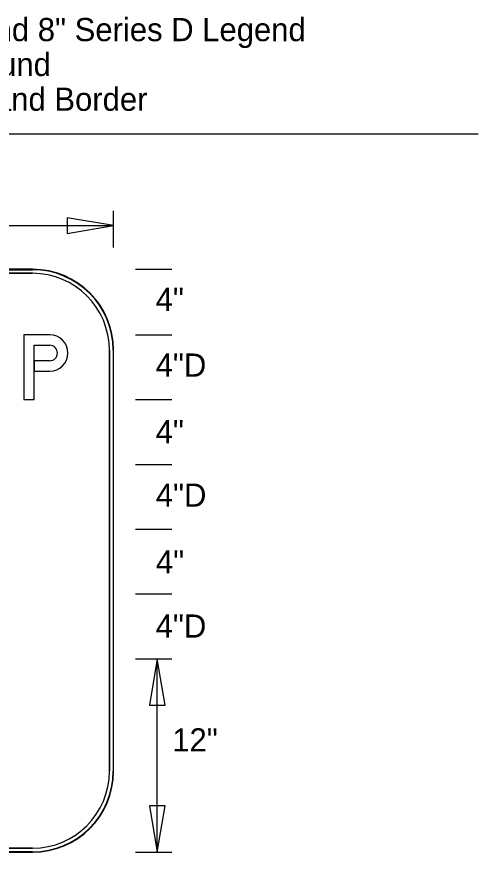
# Model space of a CAD drawing. Extents: x 0 to 770, y 0 to 495.
# Drawn here: x 700.4 to 770, y 221.6 to 347.6 of the extents above; entities that cross this region are included whole.
import ezdxf

# ---------------------------------------------------------------- set-up
doc = ezdxf.new("R2010")
doc.units = 0
for name, color, linetype in [('Dimension', 7, 'Continuous'), ('GSBWFill', 7, 'Continuous'), ('GSColorFill', 7, 'Continuous'), ('GSDims', 7, 'Continuous'), ('GSOutline', 7, 'Continuous'), ('SheetLines_dp', 7, 'Continuous'), ('TextStructures', 7, 'Continuous')]:
    doc.layers.add(name, color=color, linetype=linetype)

msp = doc.modelspace()

# ---------------------------------------------------------------- linework, layer by layer
at = {"layer": 'Dimension'}
for points in [[(714.96, 316.14), (707.95, 317.33), (707.95, 314.95)], [(721.56, 250.81), (720.37, 243.79), (722.75, 243.79)], [(721.56, 221.63), (722.75, 228.64), (720.37, 228.64)]]:
    msp.add_lwpolyline(points, close=True, dxfattribs=at)
at = {"layer": 'GSBWFill'}
for p, q in [((702.75, 309.55), (639.25, 309.55)), ((702.75, 309.55), (639.25, 309.55)), ((639.25, 308.94), (702.75, 308.94)), ((703, 298.09), (705.34, 298.09)), ((714.35, 297.34), (714.35, 233.84)), ((714.96, 233.84), (714.96, 297.34)), ((714.96, 233.84), (714.96, 297.34)), ((702.75, 222.24), (639.26, 222.24)), ((639.25, 221.63), (702.75, 221.63)), ((639.26, 221.63), (702.75, 221.63))]:
    msp.add_line(p, q, dxfattribs=at)
for points in [[(705.34, 299.66), (701.43, 299.66), (701.43, 289.89), (703, 289.89), (703, 298.09)], [(705.34, 295.75), (703, 295.75), (703, 294.19), (705.34, 294.19)]]:
    msp.add_lwpolyline(points, dxfattribs=at)
for centre, radius, start, end in [((702.75, 297.34), 12.21, 0, 90), ((702.75, 297.34), 12.21, 0, 90), ((702.75, 297.34), 11.6, 0, 90), ((705.34, 296.92), 2.74, 270, 90), ((705.34, 296.92), 1.17, 270, 90), ((702.75, 233.84), 12.21, 270, 0), ((702.75, 233.84), 11.6, 270, 0), ((702.75, 233.84), 12.21, 270, 0)]:
    msp.add_arc(centre, radius, start, end, dxfattribs=at)
at = {"layer": 'GSColorFill'}
for p, q in [((702.75, 309.55), (639.25, 309.55)), ((702.75, 309.55), (639.25, 309.55)), ((702.75, 309.55), (639.25, 309.55)), ((639.25, 309.49), (702.75, 309.49)), ((639.25, 308.94), (702.75, 308.94)), ((703, 298.09), (705.34, 298.09)), ((714.35, 297.34), (714.35, 233.84)), ((714.9, 297.34), (714.9, 233.84)), ((714.96, 233.84), (714.96, 297.34)), ((714.96, 233.84), (714.96, 297.34)), ((714.96, 233.84), (714.96, 297.34)), ((702.75, 222.24), (639.26, 222.24)), ((702.75, 221.69), (639.25, 221.69)), ((639.25, 221.63), (702.75, 221.63)), ((639.25, 221.63), (702.75, 221.63)), ((639.26, 221.63), (702.75, 221.63))]:
    msp.add_line(p, q, dxfattribs=at)
for points in [[(705.34, 299.66), (701.43, 299.66), (701.43, 289.89), (703, 289.89), (703, 298.09)], [(705.34, 295.75), (703, 295.75), (703, 294.19), (705.34, 294.19)]]:
    msp.add_lwpolyline(points, dxfattribs=at)
for centre, radius, start, end in [((702.75, 297.34), 12.21, 0, 90), ((702.75, 297.34), 12.21, 0, 90), ((702.75, 297.34), 12.21, 0, 90), ((702.75, 297.34), 12.15, 0, 90), ((702.75, 297.34), 11.6, 0, 90), ((705.34, 296.92), 2.74, 270, 90), ((705.34, 296.92), 1.17, 270, 90), ((702.75, 233.84), 12.21, 270, 0), ((702.75, 233.84), 12.21, 270, 0), ((702.75, 233.84), 11.6, 270, 0), ((702.75, 233.84), 12.21, 270, 0), ((702.75, 233.84), 12.15, 270, 0)]:
    msp.add_arc(centre, radius, start, end, dxfattribs=at)
at = {"layer": 'GSDims'}
for p, q in [((714.96, 312.85), (714.96, 318.34)), ((627.04, 316.14), (714.96, 316.14)), ((718.26, 309.55), (723.75, 309.55)), ((718.26, 299.66), (723.75, 299.66)), ((718.26, 299.66), (723.75, 299.66)), ((718.26, 289.89), (723.75, 289.89)), ((718.26, 289.89), (723.75, 289.89)), ((718.26, 280.12), (723.75, 280.12)), ((718.26, 280.12), (723.75, 280.12)), ((718.26, 270.35), (723.75, 270.35)), ((718.26, 270.35), (723.75, 270.35)), ((718.26, 260.58), (723.75, 260.58)), ((718.26, 260.58), (723.75, 260.58)), ((718.26, 250.81), (723.75, 250.81)), ((718.26, 250.81), (723.75, 250.81)), ((721.56, 221.63), (721.56, 250.81)), ((718.26, 221.63), (723.75, 221.63))]:
    msp.add_line(p, q, dxfattribs=at)
at = {"layer": 'GSOutline'}
for p, q in [((702.75, 309.55), (639.25, 309.55)), ((702.75, 309.55), (639.25, 309.55)), ((702.75, 308.94), (639.25, 308.94)), ((714.35, 233.84), (714.35, 297.34)), ((714.96, 233.84), (714.96, 297.34)), ((714.96, 233.84), (714.96, 297.34)), ((703, 294.19), (705.34, 294.19)), ((639.25, 222.24), (702.75, 222.24)), ((639.25, 221.63), (702.75, 221.63)), ((639.25, 221.63), (702.75, 221.63))]:
    msp.add_line(p, q, dxfattribs=at)
for points in [[(705.34, 299.66), (701.43, 299.66), (701.43, 289.89), (703, 289.89), (703, 294.19)], [(705.34, 295.75), (703, 295.75), (703, 298.09), (705.34, 298.09)]]:
    msp.add_lwpolyline(points, dxfattribs=at)
for centre, radius, start, end in [((702.75, 297.34), 12.21, 0, 90), ((702.75, 297.34), 12.21, 0, 90), ((702.75, 297.34), 11.6, 0, 90), ((705.34, 296.92), 2.74, 270, 90), ((705.34, 296.92), 1.17, 270, 90), ((702.75, 233.84), 12.21, 270, 0), ((702.75, 233.84), 11.6, 270, 0), ((702.75, 233.84), 12.21, 270, 0)]:
    msp.add_arc(centre, radius, start, end, dxfattribs=at)
at = {"layer": 'SheetLines_dp'}
msp.add_line((0, 330), (770, 330), dxfattribs=at)

# ---------------------------------------------------------------- texts
at = {"layer": 'TextStructures'}
for s, p in [('12" Series E and 8" Series D Legend', (667.27, 343.95)), ('White Background', (667.27, 338.7)), ('Black Legend and Border', (667.27, 333.45)), ('4"', (721.32, 303.26)), ('4"D', (721.32, 293.35)), ('4"', (721.32, 283.3)), ('4"D', (721.34, 273.74)), ('4"', (721.36, 263.68)), ('4"D', (721.32, 253.99)), ('12"', (723.83, 236.83))]:
    msp.add_text(s, height=3.5, dxfattribs=at).set_placement(p)

doc.saveas('drawing.dxf')
